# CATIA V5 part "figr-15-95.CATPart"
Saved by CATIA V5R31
Part number: Part1
Bounding box of the stored display mesh (mm): x -40 to 40, y -60 to 60, z -4 to 2
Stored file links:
  D:\PROJECTS\Project 2021\US EDITION\CATIA V5 6R 2021\Resources\Part Files\c15_catia_v5_6r2021_prt\figr-15-95.CATPart
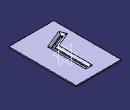
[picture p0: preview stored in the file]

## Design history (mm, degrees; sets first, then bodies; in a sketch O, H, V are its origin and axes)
SheetMetalParameters1: Thickness 2, BendRadius 4, KFactor 0.400515 {= log(min(100,max(20*SheetMetalParameters1.BendRadius,SheetMetalParameters1.Thickness)/SheetMetalParameters1.Thickness))/log(100)/2}, ReliefRadialLength 1, ReliefAxialLength 2, MinimumBendRadius 0
Body1 (main body)
  Sketch1 on xy-plane, origin (0, 0, 0), H (-1, 0, 0), V (0, -1, 0)
    line L1 (40, 60) -> (40, -60)
    line L2 (40, -60) -> (-40, -60)
    line L3 (-40, -60) -> (-40, 60)
    line L4 (-40, 60) -> (40, 60)
    length L4 = 80
    length L1 = 120
    vertical: L1 V, L3 V
    horizontal: L2 H, L4 H
    equidistance: L1 L3 O, L2 L4 O
  Wall1: Thickness 2, Profile Sketch1, OffsetValue 0
  Sketch2 on face of Wall1, origin (0, 0, 2), H (1, 0, 0), V (0, 1, 0)
    line L1 (0, 40.0798) -> (0, -21.0085)
    line L2 (0, -21.0085) -> (-27, -32)
    vertical: L1 V
  d_Stamp1: NewRoot_AttribNormalisation "No Standard", Stamp_FilletRadius 2, Stamp_IntersectFilletRadius 2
